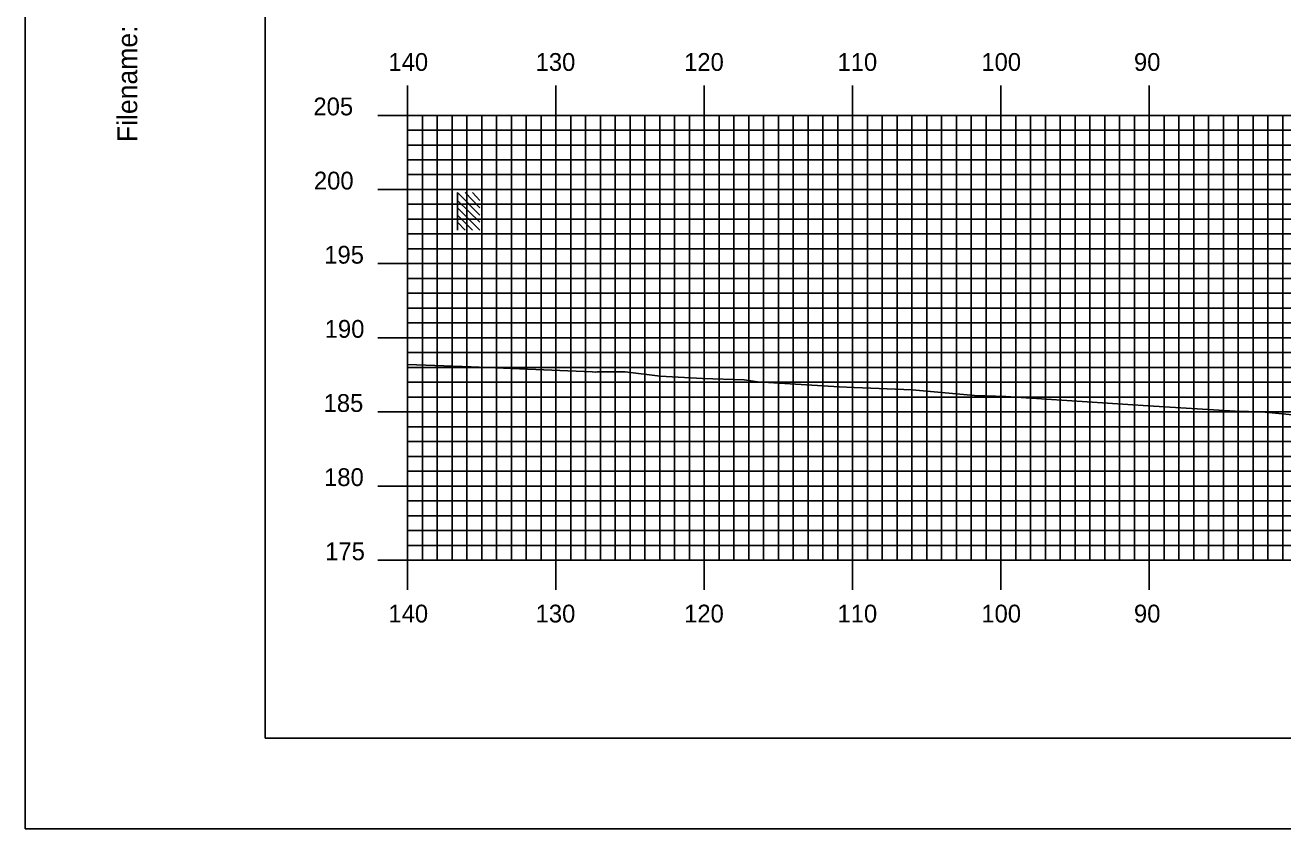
# Model space of a CAD drawing. Extents: x 1825540 to 1825883, y 442591 to 442811.
# Drawn here: x 1825540.1 to 1825624.9, y 442590.5 to 442644.7 of the extents above; entities that cross this region are included whole.
import ezdxf

# ---------------------------------------------------------------- set-up
doc = ezdxf.new("R2010")
doc.units = 0
for name, color, linetype in [('BORDER', 7, 'Continuous'), ('H_V ANNOTATION', 7, 'Continuous'), ('M_Buildings_Rooftop', 7, 'Continuous'), ('MAJOR', 7, 'Continuous'), ('MINOR', 7, 'Continuous'), ('PLOT BOUNDARY', 7, 'Continuous'), ('S_Roadway_Centerline', 7, 'Continuous')]:
    doc.layers.add(name, color=color, linetype=linetype)

msp = doc.modelspace()

# ---------------------------------------------------------------- linework, layer by layer
at = {"layer": 'BORDER'}
msp.add_lwpolyline([(1825556.274, 442596.665), (1825876.274, 442596.665), (1825876.274, 442806.665), (1825556.274, 442806.665)], close=True, dxfattribs=at)
at = {"layer": 'M_Buildings_Rooftop'}
for p, q in [((1825569.229, 442630.926), (1825569.229, 442633.452)), ((1825570.738, 442631.943), (1825569.229, 442633.452)), ((1825570.738, 442632.435), (1825569.754, 442633.452)), ((1825570.738, 442632.927), (1825570.246, 442633.452)), ((1825570.738, 442631.451), (1825569.229, 442632.927)), ((1825570.738, 442630.926), (1825569.229, 442632.435)), ((1825570.246, 442630.926), (1825569.229, 442631.943)), ((1825569.754, 442630.926), (1825569.229, 442631.451))]:
    msp.add_line(p, q, dxfattribs=at)
at = {"layer": 'MAJOR'}
for p, q in [((1825565.874, 442640.669), (1825565.874, 442638.665)), ((1825575.874, 442640.669), (1825575.874, 442638.665)), ((1825585.874, 442640.669), (1825585.874, 442638.665)), ((1825595.874, 442640.669), (1825595.874, 442638.665)), ((1825605.874, 442640.669), (1825605.874, 442638.665)), ((1825615.874, 442640.669), (1825615.874, 442638.665)), ((1825563.87, 442638.665), (1825565.874, 442638.665)), ((1825565.874, 442638.665), (1825845.874, 442638.665)), ((1825565.874, 442608.665), (1825565.874, 442638.665)), ((1825565.874, 442608.665), (1825565.874, 442638.665)), ((1825565.874, 442638.665), (1825845.874, 442638.665)), ((1825575.874, 442608.665), (1825575.874, 442638.665)), ((1825585.874, 442608.665), (1825585.874, 442638.665)), ((1825595.874, 442608.665), (1825595.874, 442638.665)), ((1825605.874, 442608.665), (1825605.874, 442638.665)), ((1825615.874, 442608.665), (1825615.874, 442638.665)), ((1825563.87, 442633.665), (1825565.874, 442633.665)), ((1825565.874, 442633.665), (1825845.874, 442633.665)), ((1825563.87, 442628.665), (1825565.874, 442628.665)), ((1825565.874, 442628.665), (1825845.874, 442628.665)), ((1825563.87, 442623.665), (1825565.874, 442623.665)), ((1825565.874, 442623.665), (1825845.874, 442623.665)), ((1825563.87, 442618.665), (1825565.874, 442618.665)), ((1825565.874, 442618.665), (1825845.874, 442618.665)), ((1825563.87, 442613.665), (1825565.874, 442613.665)), ((1825565.874, 442613.665), (1825845.874, 442613.665)), ((1825563.87, 442608.665), (1825565.874, 442608.665)), ((1825565.874, 442608.665), (1825845.874, 442608.665)), ((1825565.874, 442608.665), (1825845.874, 442608.665)), ((1825565.874, 442606.661), (1825565.874, 442608.665)), ((1825575.874, 442606.661), (1825575.874, 442608.665)), ((1825585.874, 442606.661), (1825585.874, 442608.665)), ((1825595.874, 442606.661), (1825595.874, 442608.665)), ((1825605.874, 442606.661), (1825605.874, 442608.665)), ((1825615.874, 442606.661), (1825615.874, 442608.665))]:
    msp.add_line(p, q, dxfattribs=at)
at = {"layer": 'MINOR'}
for p, q in [((1825566.874, 442608.665), (1825566.874, 442638.665)), ((1825567.874, 442608.665), (1825567.874, 442638.665)), ((1825568.874, 442608.665), (1825568.874, 442638.665)), ((1825569.874, 442608.665), (1825569.874, 442638.665)), ((1825570.874, 442608.665), (1825570.874, 442638.665)), ((1825571.874, 442608.665), (1825571.874, 442638.665)), ((1825572.874, 442608.665), (1825572.874, 442638.665)), ((1825573.874, 442608.665), (1825573.874, 442638.665)), ((1825574.874, 442608.665), (1825574.874, 442638.665)), ((1825576.874, 442608.665), (1825576.874, 442638.665)), ((1825577.874, 442608.665), (1825577.874, 442638.665)), ((1825578.874, 442608.665), (1825578.874, 442638.665)), ((1825579.874, 442608.665), (1825579.874, 442638.665)), ((1825580.874, 442608.665), (1825580.874, 442638.665)), ((1825581.874, 442608.665), (1825581.874, 442638.665)), ((1825582.874, 442608.665), (1825582.874, 442638.665)), ((1825583.874, 442608.665), (1825583.874, 442638.665)), ((1825584.874, 442608.665), (1825584.874, 442638.665)), ((1825586.874, 442608.665), (1825586.874, 442638.665)), ((1825587.874, 442608.665), (1825587.874, 442638.665)), ((1825588.874, 442608.665), (1825588.874, 442638.665)), ((1825589.874, 442608.665), (1825589.874, 442638.665)), ((1825590.874, 442608.665), (1825590.874, 442638.665)), ((1825591.874, 442608.665), (1825591.874, 442638.665)), ((1825592.874, 442608.665), (1825592.874, 442638.665)), ((1825593.874, 442608.665), (1825593.874, 442638.665)), ((1825594.874, 442608.665), (1825594.874, 442638.665)), ((1825596.874, 442608.665), (1825596.874, 442638.665)), ((1825597.874, 442608.665), (1825597.874, 442638.665)), ((1825598.874, 442608.665), (1825598.874, 442638.665)), ((1825599.874, 442608.665), (1825599.874, 442638.665)), ((1825600.874, 442608.665), (1825600.874, 442638.665)), ((1825601.874, 442608.665), (1825601.874, 442638.665)), ((1825602.874, 442608.665), (1825602.874, 442638.665)), ((1825603.874, 442608.665), (1825603.874, 442638.665)), ((1825604.874, 442608.665), (1825604.874, 442638.665)), ((1825606.874, 442608.665), (1825606.874, 442638.665)), ((1825607.874, 442608.665), (1825607.874, 442638.665)), ((1825608.874, 442608.665), (1825608.874, 442638.665)), ((1825609.874, 442608.665), (1825609.874, 442638.665)), ((1825610.874, 442608.665), (1825610.874, 442638.665)), ((1825611.874, 442608.665), (1825611.874, 442638.665)), ((1825612.874, 442608.665), (1825612.874, 442638.665)), ((1825613.874, 442608.665), (1825613.874, 442638.665)), ((1825614.874, 442608.665), (1825614.874, 442638.665)), ((1825616.874, 442608.665), (1825616.874, 442638.665)), ((1825617.874, 442608.665), (1825617.874, 442638.665)), ((1825618.874, 442608.665), (1825618.874, 442638.665)), ((1825619.874, 442608.665), (1825619.874, 442638.665)), ((1825620.874, 442608.665), (1825620.874, 442638.665)), ((1825621.874, 442608.665), (1825621.874, 442638.665)), ((1825622.874, 442608.665), (1825622.874, 442638.665)), ((1825623.874, 442608.665), (1825623.874, 442638.665)), ((1825624.874, 442608.665), (1825624.874, 442638.665)), ((1825565.874, 442637.665), (1825845.874, 442637.665)), ((1825565.874, 442637.665), (1825567.878, 442637.665)), ((1825565.874, 442636.665), (1825845.874, 442636.665)), ((1825565.874, 442636.665), (1825567.878, 442636.665)), ((1825565.874, 442635.665), (1825845.874, 442635.665)), ((1825565.874, 442635.665), (1825567.878, 442635.665)), ((1825565.874, 442634.665), (1825845.874, 442634.665)), ((1825565.874, 442634.665), (1825567.878, 442634.665)), ((1825565.874, 442632.665), (1825845.874, 442632.665)), ((1825565.874, 442632.665), (1825567.878, 442632.665)), ((1825565.874, 442631.665), (1825845.874, 442631.665)), ((1825565.874, 442631.665), (1825567.878, 442631.665)), ((1825565.874, 442630.665), (1825845.874, 442630.665)), ((1825565.874, 442630.665), (1825567.878, 442630.665)), ((1825565.874, 442629.665), (1825845.874, 442629.665)), ((1825565.874, 442629.665), (1825567.878, 442629.665)), ((1825565.874, 442627.665), (1825845.874, 442627.665)), ((1825565.874, 442627.665), (1825567.878, 442627.665)), ((1825565.874, 442626.665), (1825845.874, 442626.665)), ((1825565.874, 442626.665), (1825567.878, 442626.665)), ((1825565.874, 442625.665), (1825845.874, 442625.665)), ((1825565.874, 442625.665), (1825567.878, 442625.665)), ((1825565.874, 442624.665), (1825845.874, 442624.665)), ((1825565.874, 442624.665), (1825567.878, 442624.665)), ((1825565.874, 442622.665), (1825845.874, 442622.665)), ((1825565.874, 442622.665), (1825567.878, 442622.665)), ((1825565.874, 442621.665), (1825845.874, 442621.665)), ((1825565.874, 442621.665), (1825567.878, 442621.665)), ((1825565.874, 442620.665), (1825845.874, 442620.665)), ((1825565.874, 442620.665), (1825567.878, 442620.665)), ((1825565.874, 442619.665), (1825845.874, 442619.665)), ((1825565.874, 442619.665), (1825567.878, 442619.665)), ((1825565.874, 442617.665), (1825845.874, 442617.665)), ((1825565.874, 442617.665), (1825567.878, 442617.665)), ((1825565.874, 442616.665), (1825845.874, 442616.665)), ((1825565.874, 442616.665), (1825567.878, 442616.665)), ((1825565.874, 442615.665), (1825845.874, 442615.665)), ((1825565.874, 442615.665), (1825567.878, 442615.665)), ((1825565.874, 442614.665), (1825845.874, 442614.665)), ((1825565.874, 442614.665), (1825567.878, 442614.665)), ((1825565.874, 442612.665), (1825845.874, 442612.665)), ((1825565.874, 442612.665), (1825567.878, 442612.665)), ((1825565.874, 442611.665), (1825845.874, 442611.665)), ((1825565.874, 442611.665), (1825567.878, 442611.665)), ((1825565.874, 442610.665), (1825845.874, 442610.665)), ((1825565.874, 442610.665), (1825567.878, 442610.665)), ((1825565.874, 442609.665), (1825845.874, 442609.665)), ((1825565.874, 442609.665), (1825567.878, 442609.665))]:
    msp.add_line(p, q, dxfattribs=at)
at = {"layer": 'PLOT BOUNDARY'}
msp.add_lwpolyline([(1825540.087, 442590.547), (1825880.087, 442590.547), (1825880.087, 442810.547), (1825540.087, 442810.547)], close=True, dxfattribs=at)
msp.add_lwpolyline([(1825540.087, 442590.547), (1825880.087, 442590.547), (1825880.087, 442810.547), (1825540.087, 442810.547)], close=True, dxfattribs=at)
at = {"layer": 'S_Roadway_Centerline'}
msp.add_lwpolyline([(1825565.874, 442621.857), (1825570.154, 442621.712), (1825578.325, 442621.371), (1825578.532, 442621.336), (1825578.668, 442621.358), (1825580.535, 442621.378), (1825582.891, 442621.082), (1825585.751, 442620.922), (1825588.576, 442620.837), (1825589.46, 442620.701), (1825594.973, 442620.355), (1825595.99, 442620.301), (1825599.892, 442620.159), (1825604.091, 442619.77), (1825606.218, 442619.698), (1825615.803, 442619.073), (1825621.675, 442618.71), (1825623.466, 442618.674), (1825626.704, 442618.365)], dxfattribs=at)

# ---------------------------------------------------------------- texts
at = {"layer": 'BORDER'}
msp.add_text('Filename:', height=1.3392, rotation=90, dxfattribs=at).set_placement((1825547.644, 442636.862))
at = {"layer": 'H_V ANNOTATION'}
for s, p in [('140', (1825564.579, 442641.665)), ('130', (1825574.504, 442641.665)), ('120', (1825584.515, 442641.665)), ('110', (1825594.857, 442641.665)), ('100', (1825604.557, 442641.665)), ('90', (1825614.846, 442641.665)), ('205', (1825559.523, 442638.665)), ('200', (1825559.555, 442633.665)), ('195', (1825560.252, 442628.665)), ('190', (1825560.284, 442623.665)), ('185', (1825560.209, 442618.665)), ('180', (1825560.241, 442613.665)), ('175', (1825560.316, 442608.665)), ('140', (1825564.579, 442604.465)), ('130', (1825574.504, 442604.465)), ('120', (1825584.515, 442604.465)), ('110', (1825594.857, 442604.465)), ('100', (1825604.557, 442604.465)), ('90', (1825614.846, 442604.465))]:
    msp.add_text(s, height=1.2, dxfattribs=at).set_placement(p)
at = {"layer": 'MAJOR'}
msp.add_text('-', height=0.012, dxfattribs=at).set_placement((1825565.865, 442608.665))

doc.saveas('drawing.dxf')
